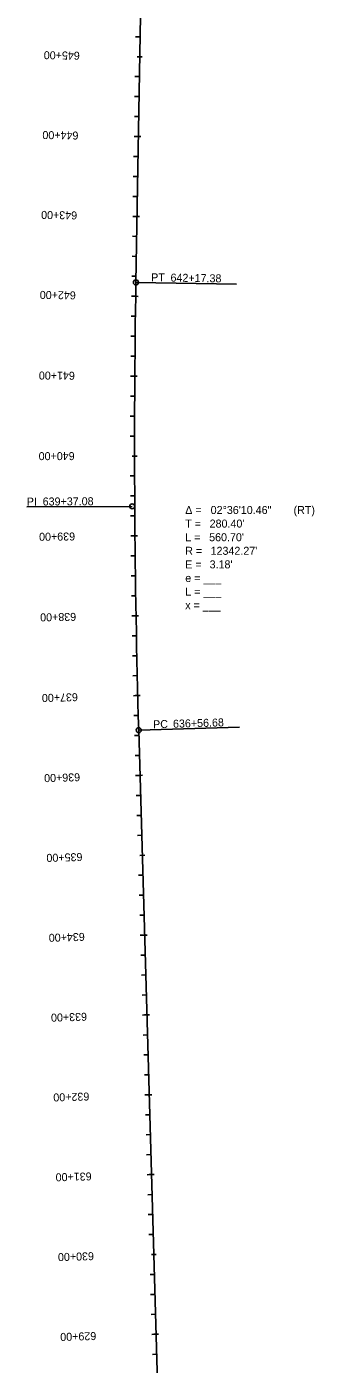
# Model space of a CAD drawing. Extents: x 23417911 to 23421158, y 6737892 to 6791804.
# Drawn here: x 23420607 to 23420967, y 6788431 to 6790106 of the extents above; entities that cross this region are included whole.
import ezdxf

# ---------------------------------------------------------------- set-up
doc = ezdxf.new("R2010")
doc.units = 0
for name, color, linetype in [('Alignment', 7, 'Continuous'), ('TextAlignment', 7, 'Continuous'), ('TextAlignmentLrg', 7, 'Continuous'), ('TextAlignmentSml', 7, 'Continuous')]:
    doc.layers.add(name, color=color, linetype=linetype)

msp = doc.modelspace()

# ---------------------------------------------------------------- linework, layer by layer
at = {"layer": 'Alignment'}
for p, q in [((23420743.8, 6789786.1), (23420756.2, 6790533.4)), ((23420743.8, 6789786.1), (23420756.2, 6790533.4)), ((23420829.7, 6786372.7), (23420747.3, 6789225.4)), ((23420829.7, 6786372.7), (23420747.3, 6789225.4))]:
    msp.add_line(p, q, dxfattribs=at)
msp.add_arc((23433084.4, 6789582), 12342.3, 179.05247, 181.65537, dxfattribs=at)
msp.add_arc((23433084.4, 6789582), 12342.3, 179.05247, 181.65537, dxfattribs=at)
at = {"layer": 'TextAlignment'}
for p, q in [((23420743.8, 6789786.1), (23420869.8, 6789784)), ((23420869.8, 6789784), (23420869.8, 6789784)), ((23420739.2, 6789505.7), (23420607.2, 6789504.9)), ((23420607.2, 6789504.9), (23420607.2, 6789504.9)), ((23420747.3, 6789225.4), (23420873.2, 6789229.1)), ((23420873.2, 6789229.1), (23420873.2, 6789229.1))]:
    msp.add_line(p, q, dxfattribs=at)
for centre in [(23420743.8, 6789786.1), (23420739.2, 6789505.7), (23420747.3, 6789225.4)]:
    msp.add_circle(centre, 3.12, dxfattribs=at)
at = {"layer": 'TextAlignmentLrg'}
for p, q in [((23420745.4, 6790068.7), (23420751.5, 6790068.6)), ((23420746.8, 6789968.7), (23420741.4, 6789968.8)), ((23420745.2, 6789868.7), (23420739.7, 6789868.8)), ((23420743.5, 6789768.7), (23420738.1, 6789768.8)), ((23420742.4, 6789668.7), (23420737, 6789668.7)), ((23420739.1, 6789568.7), (23420745.2, 6789568.7)), ((23420742.6, 6789468.7), (23420737.2, 6789468.6)), ((23420743.9, 6789368.7), (23420738.5, 6789368.6)), ((23420746.1, 6789268.7), (23420740.6, 6789268.6)), ((23420748.9, 6789168.8), (23420743.4, 6789168.6)), ((23420748.7, 6789068.7), (23420754.8, 6789068.9)), ((23420754.7, 6788968.9), (23420749.2, 6788968.7)), ((23420757.6, 6788868.9), (23420752.1, 6788868.7)), ((23420760.5, 6788768.9), (23420755, 6788768.8)), ((23420763.3, 6788669), (23420757.9, 6788668.8)), ((23420763.2, 6788568.9), (23420769.3, 6788569.1)), ((23420769.1, 6788469.1), (23420763.7, 6788468.9))]:
    msp.add_line(p, q, dxfattribs=at)
at = {"layer": 'TextAlignmentSml'}
for p, q in [((23420748.9, 6790093.6), (23420743.4, 6790093.7)), ((23420745.4, 6790068.7), (23420751.5, 6790068.6)), ((23420748.1, 6790043.7), (23420742.6, 6790043.7)), ((23420747.6, 6790018.7), (23420742.2, 6790018.7)), ((23420747.2, 6789993.7), (23420741.8, 6789993.7)), ((23420743.8, 6789968.7), (23420749.9, 6789968.6)), ((23420746.4, 6789943.7), (23420740.9, 6789943.8)), ((23420746, 6789918.7), (23420740.5, 6789918.8)), ((23420745.6, 6789893.7), (23420740.1, 6789893.8)), ((23420742.1, 6789868.7), (23420748.2, 6789868.6)), ((23420744.7, 6789843.7), (23420739.3, 6789843.8)), ((23420744.3, 6789818.7), (23420738.9, 6789818.8)), ((23420743.9, 6789793.7), (23420738.5, 6789793.8)), ((23420740.5, 6789768.7), (23420746.6, 6789768.6)), ((23420743.2, 6789743.7), (23420737.7, 6789743.8)), ((23420742.9, 6789718.7), (23420737.4, 6789718.8)), ((23420742.6, 6789693.7), (23420737.2, 6789693.7)), ((23420739.4, 6789668.7), (23420745.5, 6789668.7)), ((23420742.3, 6789643.7), (23420736.8, 6789643.7)), ((23420742.2, 6789618.7), (23420736.7, 6789618.7)), ((23420742.1, 6789593.7), (23420736.7, 6789593.7)), ((23420739.1, 6789568.7), (23420745.2, 6789568.7)), ((23420742.2, 6789543.7), (23420736.7, 6789543.7)), ((23420742.3, 6789518.7), (23420736.8, 6789518.7)), ((23420742.4, 6789493.7), (23420737, 6789493.7)), ((23420739.6, 6789468.7), (23420745.7, 6789468.7)), ((23420742.9, 6789443.7), (23420737.4, 6789443.6)), ((23420743.2, 6789418.7), (23420737.7, 6789418.6)), ((23420743.5, 6789393.7), (23420738.1, 6789393.6)), ((23420740.9, 6789368.7), (23420747, 6789368.8)), ((23420744.4, 6789343.7), (23420738.9, 6789343.6)), ((23420744.9, 6789318.7), (23420739.5, 6789318.6)), ((23420745.5, 6789293.7), (23420740, 6789293.6)), ((23420743, 6789268.7), (23420749.1, 6789268.8)), ((23420746.7, 6789243.7), (23420741.3, 6789243.6)), ((23420747.5, 6789218.7), (23420742, 6789218.6)), ((23420748.2, 6789193.8), (23420742.7, 6789193.6)), ((23420745.8, 6789168.7), (23420752, 6789168.9)), ((23420749.6, 6789143.8), (23420744.2, 6789143.6)), ((23420750.3, 6789118.8), (23420744.9, 6789118.6)), ((23420751.1, 6789093.8), (23420745.6, 6789093.6)), ((23420748.7, 6789068.7), (23420754.8, 6789068.9)), ((23420752.5, 6789043.8), (23420747, 6789043.7)), ((23420753.2, 6789018.8), (23420747.8, 6789018.7)), ((23420754, 6788993.8), (23420748.5, 6788993.7)), ((23420751.6, 6788968.8), (23420757.7, 6788968.9)), ((23420755.4, 6788943.9), (23420749.9, 6788943.7)), ((23420756.1, 6788918.9), (23420750.7, 6788918.7)), ((23420756.8, 6788893.9), (23420751.4, 6788893.7)), ((23420754.5, 6788868.8), (23420760.6, 6788869)), ((23420758.3, 6788843.9), (23420752.8, 6788843.7)), ((23420759, 6788818.9), (23420753.5, 6788818.8)), ((23420759.7, 6788793.9), (23420754.3, 6788793.8)), ((23420757.4, 6788768.8), (23420763.5, 6788769)), ((23420761.2, 6788743.9), (23420755.7, 6788743.8)), ((23420761.9, 6788719), (23420756.4, 6788718.8)), ((23420762.6, 6788694), (23420757.2, 6788693.8)), ((23420760.3, 6788668.9), (23420766.4, 6788669.1)), ((23420764.1, 6788644), (23420758.6, 6788643.8)), ((23420764.8, 6788619), (23420759.3, 6788618.8)), ((23420765.5, 6788594), (23420760, 6788593.9)), ((23420763.2, 6788568.9), (23420769.3, 6788569.1)), ((23420767, 6788544), (23420761.5, 6788543.9)), ((23420767.7, 6788519), (23420762.2, 6788518.9)), ((23420768.4, 6788494.1), (23420762.9, 6788493.9)), ((23420766.1, 6788469), (23420772.2, 6788469.2)), ((23420769.8, 6788444.1), (23420764.4, 6788443.9))]:
    msp.add_line(p, q, dxfattribs=at)

# ---------------------------------------------------------------- texts
at = {"layer": 'TextAlignment'}
for s, rotation, p in [('PT', 359.0525, (23420762.7, 6789787.5)), ('642+17.38', 359.0525, (23420787, 6789787.1)), ('PI ', 0.3539, (23420607.2, 6789506.6)), ('639+37.08', 0.3539, (23420627.1, 6789506.7)), ('PC', 1.6554, (23420765.4, 6789227.7)), ('636+56.68', 1.6554, (23420790.3, 6789228.4))]:
    msp.add_text(s, height=10.02, rotation=rotation, dxfattribs=at).set_placement(p)
for s, p in [('Δ = ', (23420805.5, 6789496.1)), ('02°36\'10.46"', (23420837.3, 6789496.1)), (' (RT)', (23420937.3, 6789496.1)), ('T = ', (23420805.5, 6789479.1)), ("280.40'", (23420836, 6789479.1)), ('L = ', (23420805.5, 6789462)), ("560.70'", (23420835.4, 6789462)), ('R = ', (23420805.5, 6789445)), ("12342.27'", (23420837.2, 6789445)), ('E = ', (23420805.5, 6789428)), ("3.18'", (23420836, 6789428)), ('e = ___ ', (23420805.5, 6789410.9)), ('L = ___', (23420805.5, 6789393.9)), ('x = ___', (23420805.5, 6789376.9))]:
    msp.add_text(s, height=10.02, dxfattribs=at).set_placement(p)
at = {"layer": 'TextAlignmentLrg'}
for s, rotation, p in [('645+00', 179.0525, (23420673.6, 6790074.9)), ('640+00', 180.0616, (23420667.1, 6789573.6)), ('635+00', 181.6554, (23420676.7, 6789071.7)), ('630+00', 181.6554, (23420691.1, 6788571.9))]:
    msp.add_text(s, height=10.02, rotation=rotation, dxfattribs=at).set_placement(p)
at = {"layer": 'TextAlignmentSml'}
for s, rotation, p in [('645+00', 179.0525, (23420673.6, 6790074.9)), ('644+00', 179.0525, (23420671.9, 6789974.9)), ('643+00', 179.0525, (23420670.3, 6789874.9)), ('642+00', 179.1332, (23420668.6, 6789774.8)), ('641+00', 179.5974, (23420667.4, 6789674.2)), ('640+00', 180.0616, (23420667.1, 6789573.6)), ('639+00', 180.5258, (23420667.6, 6789473)), ('638+00', 180.9901, (23420668.9, 6789372.4)), ('637+00', 181.4543, (23420671, 6789271.8)), ('636+00', 181.6554, (23420673.8, 6789171.6)), ('635+00', 181.6554, (23420676.7, 6789071.7)), ('634+00', 181.6554, (23420679.6, 6788971.7)), ('633+00', 181.6554, (23420682.4, 6788871.7)), ('632+00', 181.6554, (23420685.3, 6788771.8)), ('631+00', 181.6554, (23420688.2, 6788671.8)), ('630+00', 181.6554, (23420691.1, 6788571.9)), ('629+00', 181.6554, (23420694, 6788471.9))]:
    msp.add_text(s, height=10.02, rotation=rotation, dxfattribs=at).set_placement(p)

doc.saveas('drawing.dxf')
